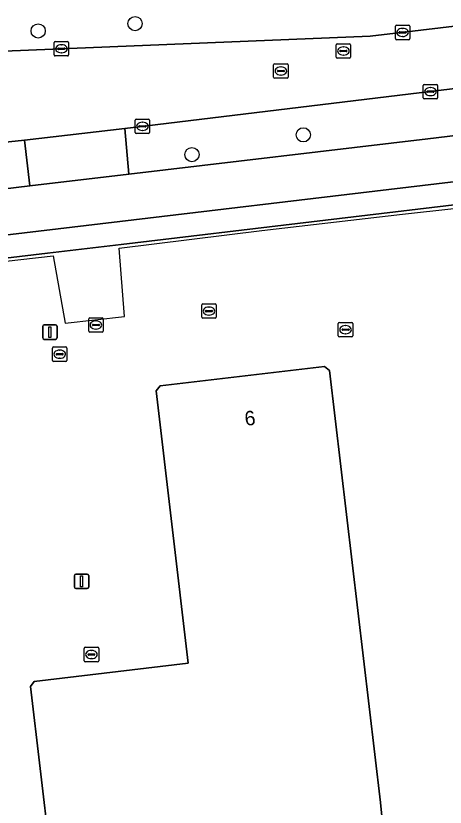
# Model space of a CAD drawing. Extents: x 161477 to 163040, y 383680 to 384871.
# Drawn here: x 161782.1 to 161811.7, y 383951.2 to 384005.8 of the extents above; entities that cross this region are included whole.
import ezdxf

# ---------------------------------------------------------------- set-up
doc = ezdxf.new("R2010")
doc.units = 0
for name, color, linetype in [('IMGEO_Berm_groen', 7, 'Continuous'), ('IMGEO_Boom', 7, 'Continuous'), ('IMGEO_Erf', 7, 'Continuous'), ('IMGEO_Fietspad_gesloten', 7, 'Continuous'), ('IMGEO_Hek', 7, 'Continuous'), ('IMGEO_Kolk', 7, 'Continuous'), ('IMGEO_Lichtmast', 7, 'Continuous'), ('IMGEO_Pand', 7, 'Continuous'), ('IMGEO_Pand_nummerreeks', 7, 'Continuous'), ('IMGEO_Rijbaan_lokaal_open', 7, 'Continuous'), ('IMGEO_Rioolput', 7, 'Continuous'), ('IMGEO_Voetpad_open', 7, 'Continuous')]:
    doc.layers.add(name, color=color, linetype=linetype)

msp = doc.modelspace()

# ---------------------------------------------------------------- linework, layer by layer
at = {"layer": 'IMGEO_Berm_groen'}
for points in [[(161763.406, 384002.679), (161774.505, 384003.101), (161806.538, 384004.391), (161824.986, 384006.585), (161828.197, 384006.984), (161829.022, 384007.117), (161838.619, 384008.665), (161849.163, 384010.365), (161855.055, 384011.424), (161855.546, 384011.497), (161856.037, 384011.57)], [(161828.903, 384001.089), (161831.245, 384002.923), (161831.22, 384003.056), (161829.549, 384002.852), (161829.007, 384002.786), (161827.026, 384002.569), (161809.92, 384000.48), (161789.593, 383998.031), (161789.883, 383994.869), (161810.506, 383997.319), (161820.233, 383998.475), (161825.487, 383999.102)]]:
    msp.add_lwpolyline(points, dxfattribs=at)
msp.add_lwpolyline([(161782.668, 383997.217), (161775.243, 383996.441), (161772.594, 383996.247), (161772.652, 383992.802), (161783.045, 383994.057)], close=True, dxfattribs=at)
at = {"layer": 'IMGEO_Boom'}
for centre in [(161790.305, 384005.266), (161783.622, 384004.761), (161801.919, 383997.589), (161794.237, 383996.223)]:
    msp.add_circle(centre, 0.489, dxfattribs=at)
at = {"layer": 'IMGEO_Erf'}
for points in [[(161815.61, 383993.149), (161789.352, 383990.026), (161784.255, 383989.42), (161776.903, 383988.545), (161782.69, 383938.808), (161821.416, 383943.334)], [(161803.384, 383981.593), (161803.738, 383981.304), (161807.24, 383951.488), (161807.35, 383950.547), (161784.759, 383947.894), (161784.419, 383948.159), (161783.095, 383959.489), (161783.353, 383959.837), (161793.982, 383961.102), (161791.758, 383979.909), (161792.036, 383980.261)]]:
    msp.add_lwpolyline(points, close=True, dxfattribs=at)
at = {"layer": 'IMGEO_Fietspad_gesloten'}
for points in [[(161825.487, 383999.102), (161820.233, 383998.475), (161810.506, 383997.319), (161789.883, 383994.869), (161783.045, 383994.057), (161772.652, 383992.802), (161763.811, 383991.819)], [(161772.22, 383989.582), (161824.85, 383995.834)]]:
    msp.add_lwpolyline(points, dxfattribs=at)
at = {"layer": 'IMGEO_Hek'}
for points in [[(161808.777, 383992.104), (161815.642, 383992.876)], [(161799.059, 383990.981), (161808.777, 383992.104)], [(161789.202, 383989.764), (161799.059, 383990.981)], [(161789.582, 383985.039), (161789.202, 383989.764)], [(161776.926, 383988.348), (161784.654, 383989.224)], [(161784.654, 383989.224), (161785.481, 383984.586)], [(161785.481, 383984.586), (161789.582, 383985.039)]]:
    msp.add_lwpolyline(points, dxfattribs=at)
at = {"layer": 'IMGEO_Kolk'}
for p, q in [((161808.272, 384004.234), (161808.272, 384005.086)), ((161808.347, 384005.16), (161809.199, 384005.16)), ((161808.76, 384004.94), (161808.785, 384004.94)), ((161809.273, 384005.086), (161809.273, 384004.234)), ((161808.531, 384004.654), (161808.531, 384004.666)), ((161808.969, 384004.617), (161808.571, 384004.617)), ((161808.574, 384004.703), (161808.972, 384004.703)), ((161808.783, 384004.38), (161808.758, 384004.38)), ((161809.015, 384004.666), (161809.015, 384004.654)), ((161784.723, 384003.107), (161784.723, 384003.959)), ((161784.798, 384004.033), (161785.65, 384004.033)), ((161785.211, 384003.813), (161785.236, 384003.813)), ((161785.724, 384003.959), (161785.724, 384003.107)), ((161809.199, 384004.16), (161808.347, 384004.16)), ((161784.982, 384003.527), (161784.982, 384003.539)), ((161785.42, 384003.49), (161785.022, 384003.49)), ((161785.025, 384003.576), (161785.423, 384003.576)), ((161785.234, 384003.253), (161785.209, 384003.253)), ((161785.466, 384003.539), (161785.466, 384003.527)), ((161785.65, 384003.033), (161784.798, 384003.033)), ((161810.266, 384001.073), (161811.118, 384001.073)), ((161810.191, 384000.147), (161810.191, 384000.999)), ((161810.45, 384000.567), (161810.45, 384000.579)), ((161810.888, 384000.53), (161810.49, 384000.53)), ((161810.493, 384000.616), (161810.891, 384000.616)), ((161810.679, 384000.853), (161810.704, 384000.853)), ((161810.934, 384000.579), (161810.934, 384000.567)), ((161811.192, 384000.999), (161811.192, 384000.147)), ((161811.118, 384000.073), (161810.266, 384000.073)), ((161810.702, 384000.293), (161810.677, 384000.293)), ((161790.314, 383997.752), (161790.314, 383998.604)), ((161790.389, 383998.678), (161791.241, 383998.678)), ((161790.802, 383998.458), (161790.827, 383998.458)), ((161791.315, 383998.604), (161791.315, 383997.752)), ((161790.573, 383998.172), (161790.573, 383998.184)), ((161791.011, 383998.135), (161790.613, 383998.135)), ((161790.616, 383998.221), (161791.014, 383998.221)), ((161790.825, 383997.898), (161790.8, 383997.898)), ((161791.057, 383998.184), (161791.057, 383998.172)), ((161791.241, 383997.678), (161790.389, 383997.678)), ((161794.909, 383984.992), (161794.909, 383985.844)), ((161794.984, 383985.918), (161795.836, 383985.918)), ((161795.91, 383985.844), (161795.91, 383984.992)), ((161795.168, 383985.412), (161795.168, 383985.424)), ((161795.606, 383985.375), (161795.208, 383985.375)), ((161795.211, 383985.461), (161795.609, 383985.461)), ((161795.397, 383985.698), (161795.422, 383985.698)), ((161795.652, 383985.424), (161795.652, 383985.412)), ((161787.108, 383984.027), (161787.108, 383984.879)), ((161787.183, 383984.953), (161788.035, 383984.953)), ((161787.596, 383984.733), (161787.621, 383984.733)), ((161788.109, 383984.879), (161788.109, 383984.027)), ((161795.836, 383984.918), (161794.984, 383984.918)), ((161795.42, 383985.138), (161795.395, 383985.138)), ((161787.367, 383984.447), (161787.367, 383984.459)), ((161787.805, 383984.41), (161787.407, 383984.41)), ((161787.41, 383984.496), (161787.808, 383984.496)), ((161787.619, 383984.173), (161787.594, 383984.173)), ((161787.851, 383984.459), (161787.851, 383984.447)), ((161804.336, 383983.705), (161804.336, 383984.557)), ((161804.411, 383984.631), (161805.263, 383984.631)), ((161804.595, 383984.125), (161804.595, 383984.137)), ((161804.638, 383984.174), (161805.036, 383984.174)), ((161804.824, 383984.411), (161804.849, 383984.411)), ((161805.079, 383984.137), (161805.079, 383984.125)), ((161805.337, 383984.557), (161805.337, 383983.705)), ((161788.035, 383983.953), (161787.183, 383983.953)), ((161805.263, 383983.631), (161804.411, 383983.631)), ((161805.033, 383984.088), (161804.635, 383984.088)), ((161804.847, 383983.851), (161804.822, 383983.851)), ((161784.607, 383982.014), (161784.607, 383982.866)), ((161784.682, 383982.94), (161785.534, 383982.94)), ((161784.909, 383982.483), (161785.307, 383982.483)), ((161785.095, 383982.72), (161785.12, 383982.72)), ((161785.608, 383982.866), (161785.608, 383982.014)), ((161785.534, 383981.94), (161784.682, 383981.94)), ((161784.866, 383982.434), (161784.866, 383982.446)), ((161785.304, 383982.397), (161784.906, 383982.397)), ((161785.118, 383982.16), (161785.093, 383982.16)), ((161785.35, 383982.446), (161785.35, 383982.434)), ((161786.799, 383961.275), (161786.799, 383962.127)), ((161786.874, 383962.201), (161787.726, 383962.201)), ((161787.058, 383961.695), (161787.058, 383961.707)), ((161787.101, 383961.744), (161787.499, 383961.744)), ((161787.287, 383961.981), (161787.312, 383961.981)), ((161787.542, 383961.707), (161787.542, 383961.695)), ((161787.8, 383962.127), (161787.8, 383961.275)), ((161787.726, 383961.201), (161786.874, 383961.201)), ((161787.496, 383961.658), (161787.098, 383961.658)), ((161787.31, 383961.421), (161787.285, 383961.421))]:
    msp.add_line(p, q, dxfattribs=at)
for points in [[(161808.272, 384004.234), (161808.272, 384005.086)], [(161808.347, 384005.16), (161809.199, 384005.16)], [(161809.273, 384005.086), (161809.273, 384004.234)], [(161784.723, 384003.107), (161784.723, 384003.959)], [(161784.798, 384004.033), (161785.65, 384004.033)], [(161785.724, 384003.959), (161785.724, 384003.107)], [(161809.199, 384004.16), (161808.347, 384004.16)], [(161785.65, 384003.033), (161784.798, 384003.033)], [(161810.266, 384001.073), (161811.118, 384001.073)], [(161810.191, 384000.147), (161810.191, 384000.999)], [(161811.192, 384000.999), (161811.192, 384000.147)], [(161811.118, 384000.073), (161810.266, 384000.073)], [(161790.314, 383997.752), (161790.314, 383998.604)], [(161790.389, 383998.678), (161791.241, 383998.678)], [(161791.315, 383998.604), (161791.315, 383997.752)], [(161791.241, 383997.678), (161790.389, 383997.678)], [(161794.909, 383984.992), (161794.909, 383985.844)], [(161794.984, 383985.918), (161795.836, 383985.918)], [(161795.91, 383985.844), (161795.91, 383984.992)], [(161787.108, 383984.027), (161787.108, 383984.879)], [(161787.183, 383984.953), (161788.035, 383984.953)], [(161788.109, 383984.879), (161788.109, 383984.027)], [(161795.836, 383984.918), (161794.984, 383984.918)], [(161804.336, 383983.705), (161804.336, 383984.557)], [(161804.411, 383984.631), (161805.263, 383984.631)], [(161805.337, 383984.557), (161805.337, 383983.705)], [(161788.035, 383983.953), (161787.183, 383983.953)], [(161805.263, 383983.631), (161804.411, 383983.631)], [(161784.607, 383982.014), (161784.607, 383982.866)], [(161784.682, 383982.94), (161785.534, 383982.94)], [(161785.608, 383982.866), (161785.608, 383982.014)], [(161785.534, 383981.94), (161784.682, 383981.94)], [(161786.799, 383961.275), (161786.799, 383962.127)], [(161786.874, 383962.201), (161787.726, 383962.201)], [(161787.8, 383962.127), (161787.8, 383961.275)], [(161787.726, 383961.201), (161786.874, 383961.201)]]:
    msp.add_lwpolyline(points, dxfattribs=at)
for centre, radius, start, end in [((161808.349, 384005.084), 0.0765, 91.552, 178.448), ((161808.349, 384005.084), 0.0765, 91.552, 178.448), ((161809.197, 384005.084), 0.0765, 1.552, 88.448), ((161809.197, 384005.084), 0.0765, 1.552, 88.448), ((161808.571, 384004.663), 0.0403, 85.8775, 175.7526), ((161808.568, 384004.653), 0.0366, 178.938, 274.7102), ((161808.972, 384004.66), 0.043, 264.8664, 352.4533), ((161808.976, 384004.665), 0.0386, 1.7309, 96.639), ((161784.8, 384003.957), 0.0765, 91.552, 178.448), ((161784.8, 384003.957), 0.0765, 91.552, 178.448), ((161785.648, 384003.957), 0.0765, 1.552, 88.448), ((161785.648, 384003.957), 0.0765, 1.552, 88.448), ((161808.349, 384004.236), 0.0765, 181.552, 268.448), ((161808.349, 384004.236), 0.0765, 181.552, 268.448), ((161809.197, 384004.236), 0.0765, 271.552, 358.448), ((161809.197, 384004.236), 0.0765, 271.552, 358.448), ((161785.022, 384003.536), 0.0403, 85.8775, 175.7526), ((161785.019, 384003.526), 0.0366, 178.938, 274.7102), ((161785.423, 384003.533), 0.043, 264.8664, 352.4533), ((161785.427, 384003.538), 0.0386, 1.7309, 96.639), ((161784.8, 384003.109), 0.0765, 181.552, 268.448), ((161784.8, 384003.109), 0.0765, 181.552, 268.448), ((161785.648, 384003.109), 0.0765, 271.552, 358.448), ((161785.648, 384003.109), 0.0765, 271.552, 358.448), ((161810.268, 384000.997), 0.0765, 91.552, 178.448), ((161810.268, 384000.997), 0.0765, 91.552, 178.448), ((161811.116, 384000.997), 0.0765, 1.552, 88.448), ((161811.116, 384000.997), 0.0765, 1.552, 88.448), ((161810.49, 384000.576), 0.0403, 85.8775, 175.7526), ((161810.487, 384000.566), 0.0366, 178.938, 274.7102), ((161810.891, 384000.573), 0.043, 264.8664, 352.4533), ((161810.895, 384000.578), 0.0386, 1.7309, 96.639), ((161810.268, 384000.149), 0.0765, 181.552, 268.448), ((161810.268, 384000.149), 0.0765, 181.552, 268.448), ((161811.116, 384000.149), 0.0765, 271.552, 358.448), ((161811.116, 384000.149), 0.0765, 271.552, 358.448), ((161790.391, 383998.602), 0.0765, 91.552, 178.448), ((161790.391, 383998.602), 0.0765, 91.552, 178.448), ((161791.239, 383998.602), 0.0765, 1.552, 88.448), ((161791.239, 383998.602), 0.0765, 1.552, 88.448), ((161790.613, 383998.181), 0.0403, 85.8775, 175.7526), ((161790.61, 383998.171), 0.0366, 178.938, 274.7102), ((161791.014, 383998.178), 0.043, 264.8664, 352.4533), ((161791.018, 383998.183), 0.0386, 1.7309, 96.639), ((161790.391, 383997.754), 0.0765, 181.552, 268.448), ((161790.391, 383997.754), 0.0765, 181.552, 268.448), ((161791.239, 383997.754), 0.0765, 271.552, 358.448), ((161791.239, 383997.754), 0.0765, 271.552, 358.448), ((161794.986, 383985.842), 0.0765, 91.552, 178.448), ((161794.986, 383985.842), 0.0765, 91.552, 178.448), ((161795.834, 383985.842), 0.0765, 1.552, 88.448), ((161795.834, 383985.842), 0.0765, 1.552, 88.448), ((161795.208, 383985.421), 0.0403, 85.8775, 175.7526), ((161795.205, 383985.411), 0.0366, 178.938, 274.7102), ((161795.609, 383985.418), 0.043, 264.8664, 352.4533), ((161795.613, 383985.423), 0.0386, 1.7309, 96.639), ((161787.185, 383984.877), 0.0765, 91.552, 178.448), ((161787.185, 383984.877), 0.0765, 91.552, 178.448), ((161788.033, 383984.877), 0.0765, 1.552, 88.448), ((161788.033, 383984.877), 0.0765, 1.552, 88.448), ((161794.986, 383984.994), 0.0765, 181.552, 268.448), ((161794.986, 383984.994), 0.0765, 181.552, 268.448), ((161795.834, 383984.994), 0.0765, 271.552, 358.448), ((161795.834, 383984.994), 0.0765, 271.552, 358.448), ((161787.407, 383984.456), 0.0403, 85.8775, 175.7526), ((161787.404, 383984.446), 0.0366, 178.938, 274.7102), ((161787.808, 383984.453), 0.043, 264.8664, 352.4533), ((161787.812, 383984.458), 0.0386, 1.7309, 96.639), ((161804.413, 383984.555), 0.0765, 91.552, 178.448), ((161804.413, 383984.555), 0.0765, 91.552, 178.448), ((161804.635, 383984.134), 0.0403, 85.8775, 175.7526), ((161804.632, 383984.124), 0.0366, 178.938, 274.7102), ((161805.036, 383984.131), 0.043, 264.8664, 352.4533), ((161805.04, 383984.136), 0.0386, 1.7309, 96.639), ((161805.261, 383984.555), 0.0765, 1.552, 88.448), ((161805.261, 383984.555), 0.0765, 1.552, 88.448), ((161787.185, 383984.029), 0.0765, 181.552, 268.448), ((161787.185, 383984.029), 0.0765, 181.552, 268.448), ((161788.033, 383984.029), 0.0765, 271.552, 358.448), ((161788.033, 383984.029), 0.0765, 271.552, 358.448), ((161804.413, 383983.707), 0.0765, 181.552, 268.448), ((161804.413, 383983.707), 0.0765, 181.552, 268.448), ((161805.261, 383983.707), 0.0765, 271.552, 358.448), ((161805.261, 383983.707), 0.0765, 271.552, 358.448), ((161784.684, 383982.864), 0.0765, 91.552, 178.448), ((161784.684, 383982.864), 0.0765, 91.552, 178.448), ((161784.906, 383982.443), 0.0403, 85.8775, 175.7526), ((161785.311, 383982.445), 0.0386, 1.7309, 96.639), ((161785.532, 383982.864), 0.0765, 1.552, 88.448), ((161785.532, 383982.864), 0.0765, 1.552, 88.448), ((161784.684, 383982.016), 0.0765, 181.552, 268.448), ((161784.684, 383982.016), 0.0765, 181.552, 268.448), ((161784.903, 383982.433), 0.0366, 178.938, 274.7102), ((161785.307, 383982.44), 0.043, 264.8664, 352.4533), ((161785.532, 383982.016), 0.0765, 271.552, 358.448), ((161785.532, 383982.016), 0.0765, 271.552, 358.448), ((161786.876, 383962.125), 0.0765, 91.552, 178.448), ((161786.876, 383962.125), 0.0765, 91.552, 178.448), ((161787.098, 383961.704), 0.0403, 85.8775, 175.7526), ((161787.503, 383961.706), 0.0386, 1.7309, 96.639), ((161787.724, 383962.125), 0.0765, 1.552, 88.448), ((161787.724, 383962.125), 0.0765, 1.552, 88.448), ((161786.876, 383961.277), 0.0765, 181.552, 268.448), ((161786.876, 383961.277), 0.0765, 181.552, 268.448), ((161787.095, 383961.694), 0.0366, 178.938, 274.7102), ((161787.499, 383961.701), 0.043, 264.8664, 352.4533), ((161787.724, 383961.277), 0.0765, 271.552, 358.448), ((161787.724, 383961.277), 0.0765, 271.552, 358.448)]:
    msp.add_arc(centre, radius, start, end, dxfattribs=at)
for centre, major_axis, ratio, start_param, end_param in [((161808.759, 384004.66), (-0.387, 0.002), 0.722429, 4.712389, 7.853982), ((161808.784, 384004.66), (-0.39, 0.002), 0.717154, 1.570796, 4.712389), ((161785.21, 384003.533), (-0.387, 0.002), 0.722429, 4.712389, 7.853982), ((161785.235, 384003.533), (-0.39, 0.002), 0.717154, 1.570796, 4.712389), ((161810.678, 384000.573), (-0.387, 0.002), 0.722429, 4.712389, 7.853982), ((161810.703, 384000.573), (-0.39, 0.002), 0.717154, 1.570796, 4.712389), ((161790.801, 383998.178), (-0.387, 0.002), 0.722429, 4.712389, 7.853982), ((161790.826, 383998.178), (-0.39, 0.002), 0.717154, 1.570796, 4.712389), ((161795.396, 383985.418), (-0.387, 0.002), 0.722429, 4.712389, 7.853982), ((161795.421, 383985.418), (-0.39, 0.002), 0.717154, 1.570796, 4.712389), ((161787.595, 383984.453), (-0.387, 0.002), 0.722429, 4.712389, 7.853982), ((161787.62, 383984.453), (-0.39, 0.002), 0.717154, 1.570796, 4.712389), ((161804.823, 383984.131), (-0.387, 0.002), 0.722429, 4.712389, 7.853982), ((161804.848, 383984.131), (-0.39, 0.002), 0.717154, 1.570796, 4.712389), ((161785.094, 383982.44), (-0.387, 0.002), 0.722429, 4.712389, 7.853982), ((161785.119, 383982.44), (-0.39, 0.002), 0.717154, 1.570796, 4.712389), ((161787.286, 383961.701), (-0.387, 0.002), 0.722429, 4.712389, 7.853982), ((161787.311, 383961.701), (-0.39, 0.002), 0.717154, 1.570796, 4.712389)]:
    msp.add_ellipse(centre, major_axis=major_axis, ratio=ratio, start_param=start_param, end_param=end_param, dxfattribs=at)
at = {"layer": 'IMGEO_Lichtmast'}
for p, q in [((161783.933, 383983.564), (161783.933, 383984.364)), ((161783.933, 383984.364), (161783.933, 383983.564)), ((161784.033, 383984.464), (161784.823, 383984.464)), ((161784.823, 383984.464), (161784.033, 383984.464)), ((161784.923, 383984.364), (161784.923, 383983.564)), ((161784.923, 383983.564), (161784.923, 383984.364)), ((161784.823, 383983.464), (161784.033, 383983.464)), ((161784.033, 383983.464), (161784.823, 383983.464)), ((161786.22, 383967.26), (161787.01, 383967.26)), ((161787.01, 383967.26), (161786.22, 383967.26)), ((161786.12, 383966.36), (161786.12, 383967.16)), ((161786.12, 383967.16), (161786.12, 383966.36)), ((161787.11, 383967.16), (161787.11, 383966.36)), ((161787.11, 383966.36), (161787.11, 383967.16)), ((161787.01, 383966.26), (161786.22, 383966.26)), ((161786.22, 383966.26), (161787.01, 383966.26))]:
    msp.add_line(p, q, dxfattribs=at)
for points in [[(161784.353, 383984.339), (161784.503, 383984.339), (161784.503, 383983.589), (161784.353, 383983.589), (161784.353, 383984.339)], [(161786.54, 383967.135), (161786.69, 383967.135), (161786.69, 383966.385), (161786.54, 383966.385), (161786.54, 383967.135)]]:
    msp.add_lwpolyline(points, dxfattribs=at)
for centre, start, end in [((161784.033, 383984.364), 90, 180), ((161784.033, 383984.364), 90, 180), ((161784.823, 383984.364), 0, 90), ((161784.823, 383984.364), 360, 90), ((161784.033, 383983.564), 180, 270), ((161784.033, 383983.564), 180, 270), ((161784.823, 383983.564), 270, 0), ((161784.823, 383983.564), 270, 0), ((161786.22, 383967.16), 90, 180), ((161786.22, 383967.16), 90, 180), ((161787.01, 383967.16), 0, 90), ((161787.01, 383967.16), 360, 90), ((161786.22, 383966.36), 180, 270), ((161786.22, 383966.36), 180, 270), ((161787.01, 383966.36), 270, 0), ((161787.01, 383966.36), 270, 0)]:
    msp.add_arc(centre, 0.1, start, end, dxfattribs=at)
at = {"layer": 'IMGEO_Pand'}
msp.add_lwpolyline([(161803.738, 383981.304), (161803.384, 383981.593), (161792.036, 383980.261), (161791.758, 383979.909), (161793.982, 383961.102), (161783.353, 383959.837), (161783.095, 383959.489), (161784.419, 383948.159), (161784.759, 383947.894), (161807.35, 383950.547), (161807.24, 383951.488)], close=True, dxfattribs=at)
at = {"layer": 'IMGEO_Rijbaan_lokaal_open'}
msp.add_lwpolyline([(161827.026, 384002.569), (161829.007, 384002.786), (161829.549, 384002.852), (161829.022, 384007.117), (161828.197, 384006.984), (161824.986, 384006.585), (161806.538, 384004.391), (161774.505, 384003.101), (161775.243, 383996.441), (161782.668, 383997.217), (161789.593, 383998.031), (161809.92, 384000.48)], close=True, dxfattribs=at)
at = {"layer": 'IMGEO_Rioolput'}
for p, q in [((161804.186, 384002.954), (161804.186, 384003.806)), ((161804.261, 384003.88), (161805.113, 384003.88)), ((161805.187, 384003.806), (161805.187, 384002.954)), ((161804.445, 384003.374), (161804.445, 384003.386)), ((161804.883, 384003.337), (161804.485, 384003.337)), ((161804.488, 384003.423), (161804.886, 384003.423)), ((161804.674, 384003.66), (161804.699, 384003.66)), ((161804.929, 384003.386), (161804.929, 384003.374)), ((161805.113, 384002.88), (161804.261, 384002.88)), ((161804.697, 384003.1), (161804.672, 384003.1)), ((161799.87, 384001.571), (161799.87, 384002.423)), ((161799.945, 384002.497), (161800.797, 384002.497)), ((161800.358, 384002.277), (161800.383, 384002.277)), ((161800.871, 384002.423), (161800.871, 384001.571)), ((161800.129, 384001.991), (161800.129, 384002.003)), ((161800.567, 384001.954), (161800.169, 384001.954)), ((161800.172, 384002.04), (161800.57, 384002.04)), ((161800.381, 384001.717), (161800.356, 384001.717)), ((161800.613, 384002.003), (161800.613, 384001.991)), ((161800.797, 384001.497), (161799.945, 384001.497))]:
    msp.add_line(p, q, dxfattribs=at)
for points in [[(161804.186, 384002.954), (161804.186, 384003.806)], [(161804.261, 384003.88), (161805.113, 384003.88)], [(161805.187, 384003.806), (161805.187, 384002.954)], [(161805.113, 384002.88), (161804.261, 384002.88)], [(161799.87, 384001.571), (161799.87, 384002.423)], [(161799.945, 384002.497), (161800.797, 384002.497)], [(161800.871, 384002.423), (161800.871, 384001.571)], [(161800.797, 384001.497), (161799.945, 384001.497)]]:
    msp.add_lwpolyline(points, dxfattribs=at)
for centre, radius, start, end in [((161804.263, 384003.804), 0.0765, 91.552, 178.448), ((161804.263, 384003.804), 0.0765, 91.552, 178.448), ((161805.111, 384003.804), 0.0765, 1.552, 88.448), ((161805.111, 384003.804), 0.0765, 1.552, 88.448), ((161804.485, 384003.383), 0.0403, 85.8775, 175.7526), ((161804.482, 384003.373), 0.0366, 178.938, 274.7102), ((161804.886, 384003.38), 0.043, 264.8664, 352.4533), ((161804.89, 384003.385), 0.0386, 1.7309, 96.639), ((161804.263, 384002.956), 0.0765, 181.552, 268.448), ((161804.263, 384002.956), 0.0765, 181.552, 268.448), ((161805.111, 384002.956), 0.0765, 271.552, 358.448), ((161805.111, 384002.956), 0.0765, 271.552, 358.448), ((161799.947, 384002.421), 0.0765, 91.552, 178.448), ((161799.947, 384002.421), 0.0765, 91.552, 178.448), ((161800.795, 384002.421), 0.0765, 1.552, 88.448), ((161800.795, 384002.421), 0.0765, 1.552, 88.448), ((161800.169, 384002), 0.0403, 85.8775, 175.7526), ((161800.166, 384001.99), 0.0366, 178.938, 274.7102), ((161800.57, 384001.997), 0.043, 264.8664, 352.4533), ((161800.574, 384002.002), 0.0386, 1.7309, 96.639), ((161799.947, 384001.573), 0.0765, 181.552, 268.448), ((161799.947, 384001.573), 0.0765, 181.552, 268.448), ((161800.795, 384001.573), 0.0765, 271.552, 358.448), ((161800.795, 384001.573), 0.0765, 271.552, 358.448)]:
    msp.add_arc(centre, radius, start, end, dxfattribs=at)
for centre, major_axis, ratio, start_param, end_param in [((161804.673, 384003.38), (-0.387, 0.002), 0.722429, 4.712389, 7.853982), ((161804.698, 384003.38), (-0.39, 0.002), 0.717154, 1.570796, 4.712389), ((161800.357, 384001.997), (-0.387, 0.002), 0.722429, 4.712389, 7.853982), ((161800.382, 384001.997), (-0.39, 0.002), 0.717154, 1.570796, 4.712389)]:
    msp.add_ellipse(centre, major_axis=major_axis, ratio=ratio, start_param=start_param, end_param=end_param, dxfattribs=at)
at = {"layer": 'IMGEO_Voetpad_open'}
msp.add_lwpolyline([(161789.593, 383998.031), (161782.668, 383997.217), (161783.045, 383994.057), (161789.883, 383994.869)], close=True, dxfattribs=at)
for points in [[(161833.796, 383996.89), (161824.85, 383995.834), (161772.22, 383989.582)], [(161761.344, 383986.871), (161765.091, 383987.162), (161771.73, 383987.931), (161773.511, 383988.142), (161776.903, 383988.545), (161784.255, 383989.42), (161789.352, 383990.026), (161815.61, 383993.149), (161816.483, 383993.253), (161821.039, 383987.146), (161821.21, 383987.165)]]:
    msp.add_lwpolyline(points, dxfattribs=at)

# ---------------------------------------------------------------- texts
at = {"layer": 'IMGEO_Pand_nummerreeks'}
msp.add_text('6', height=1, rotation=6.6291, dxfattribs=at).set_placement((161797.926, 383977.486))

doc.saveas('drawing.dxf')
